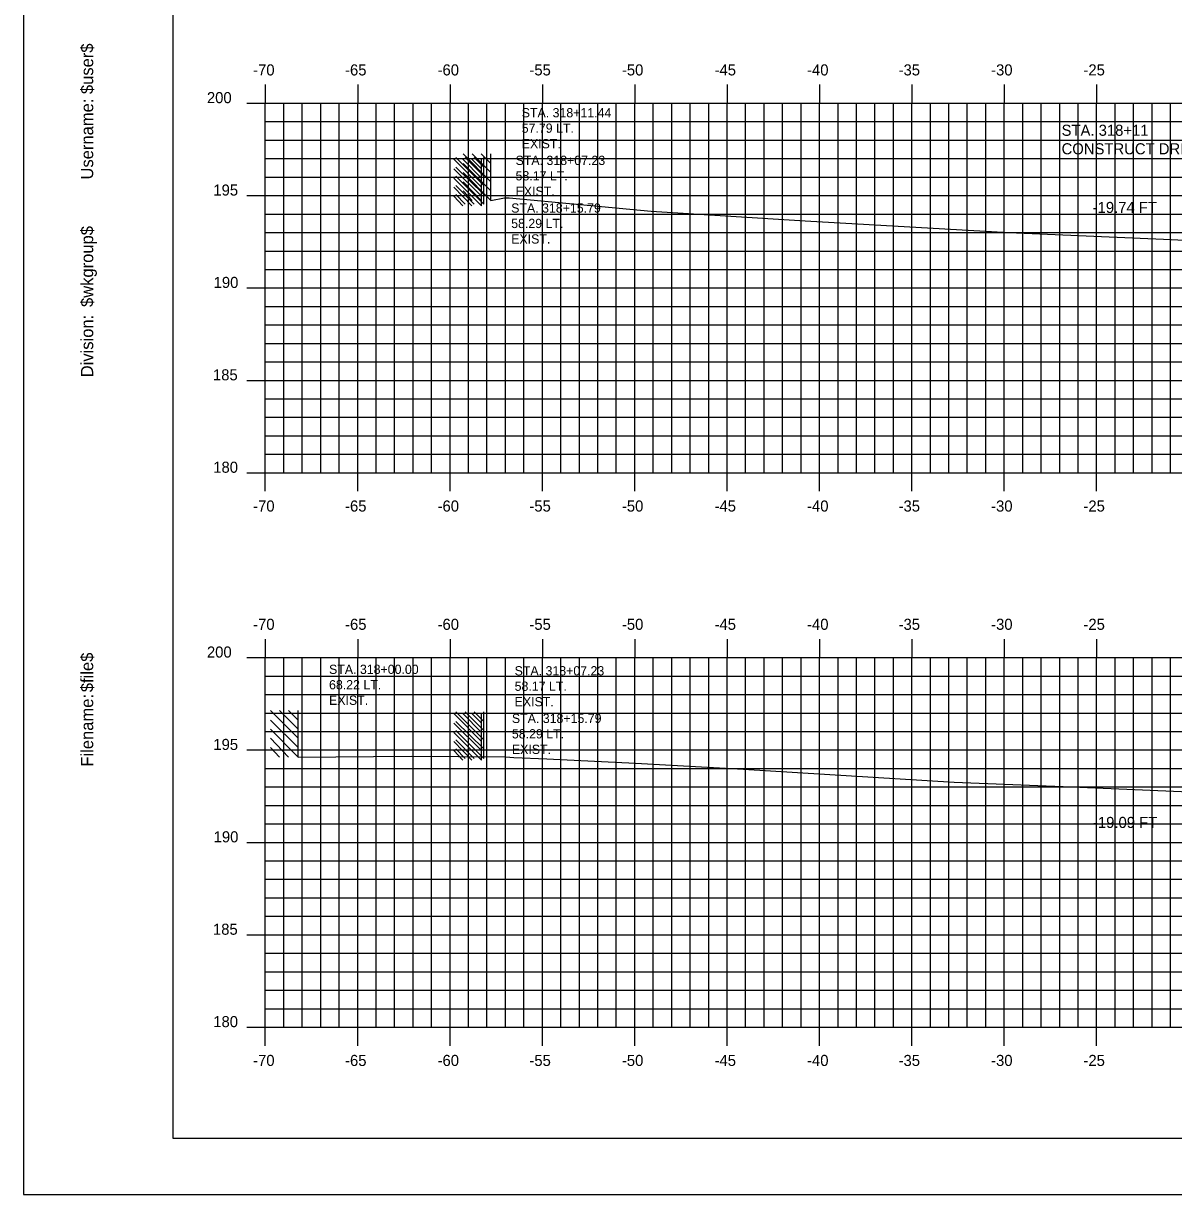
# Model space of a CAD drawing. Extents: x 1139207 to 1139377, y 608981 to 609091.
# Drawn here: x 1139206.6 to 1139268.9, y 608981.3 to 609044.6 of the extents above; entities that cross this region are included whole.
import ezdxf

# ---------------------------------------------------------------- set-up
doc = ezdxf.new("R2010")
doc.units = 0
for name, color, linetype in [('ANNOTATION', 7, 'Continuous'), ('BORDER', 7, 'Continuous'), ('D_Text_Monospaced', 7, 'Continuous'), ('D_Text_Standard', 7, 'Continuous'), ('H_V ANNOTATION', 7, 'Continuous'), ('MAJOR', 7, 'Continuous'), ('MINOR', 7, 'Continuous'), ('PLOT BOUNDARY', 7, 'Continuous'), ('S_Buildings', 7, 'Continuous'), ('S_Buildings_SillElevation', 7, 'Continuous'), ('S_Roadway_Centerline', 7, 'Continuous')]:
    doc.layers.add(name, color=color, linetype=linetype)

msp = doc.modelspace()

# ---------------------------------------------------------------- linework, layer by layer
at = {"layer": 'BORDER'}
msp.add_lwpolyline([(1139214.705, 608984.335), (1139374.705, 608984.335), (1139374.705, 609089.335), (1139214.705, 609089.335)], close=True, dxfattribs=at)
at = {"layer": 'MAJOR'}
for p, q in [((1139219.705, 609041.337), (1139219.705, 609040.335)), ((1139224.705, 609041.337), (1139224.705, 609040.335)), ((1139229.705, 609041.337), (1139229.705, 609040.335)), ((1139234.705, 609041.337), (1139234.705, 609040.335)), ((1139239.705, 609041.337), (1139239.705, 609040.335)), ((1139244.705, 609041.337), (1139244.705, 609040.335)), ((1139249.705, 609041.337), (1139249.705, 609040.335)), ((1139254.705, 609041.337), (1139254.705, 609040.335)), ((1139259.705, 609041.337), (1139259.705, 609040.335)), ((1139264.705, 609041.337), (1139264.705, 609040.335)), ((1139218.703, 609040.335), (1139219.705, 609040.335)), ((1139219.705, 609040.335), (1139359.705, 609040.335)), ((1139219.705, 609020.335), (1139219.705, 609040.335)), ((1139219.705, 609020.335), (1139219.705, 609040.335)), ((1139219.705, 609040.335), (1139359.705, 609040.335)), ((1139224.705, 609020.335), (1139224.705, 609040.335)), ((1139229.705, 609020.335), (1139229.705, 609040.335)), ((1139234.705, 609020.335), (1139234.705, 609040.335)), ((1139239.705, 609020.335), (1139239.705, 609040.335)), ((1139244.705, 609020.335), (1139244.705, 609040.335)), ((1139249.705, 609020.335), (1139249.705, 609040.335)), ((1139254.705, 609020.335), (1139254.705, 609040.335)), ((1139259.705, 609020.335), (1139259.705, 609040.335)), ((1139264.705, 609020.335), (1139264.705, 609040.335)), ((1139218.703, 609035.335), (1139219.705, 609035.335)), ((1139219.705, 609035.335), (1139359.705, 609035.335)), ((1139218.703, 609030.335), (1139219.705, 609030.335)), ((1139219.705, 609030.335), (1139359.705, 609030.335)), ((1139218.703, 609025.335), (1139219.705, 609025.335)), ((1139219.705, 609025.335), (1139359.705, 609025.335)), ((1139218.703, 609020.335), (1139219.705, 609020.335)), ((1139219.705, 609020.335), (1139359.705, 609020.335)), ((1139219.705, 609020.335), (1139359.705, 609020.335)), ((1139219.705, 609019.333), (1139219.705, 609020.335)), ((1139224.705, 609019.333), (1139224.705, 609020.335)), ((1139229.705, 609019.333), (1139229.705, 609020.335)), ((1139234.705, 609019.333), (1139234.705, 609020.335)), ((1139239.705, 609019.333), (1139239.705, 609020.335)), ((1139244.705, 609019.333), (1139244.705, 609020.335)), ((1139249.705, 609019.333), (1139249.705, 609020.335)), ((1139254.705, 609019.333), (1139254.705, 609020.335)), ((1139259.705, 609019.333), (1139259.705, 609020.335)), ((1139264.705, 609019.333), (1139264.705, 609020.335)), ((1139219.705, 609011.337), (1139219.705, 609010.335)), ((1139224.705, 609011.337), (1139224.705, 609010.335)), ((1139229.705, 609011.337), (1139229.705, 609010.335)), ((1139234.705, 609011.337), (1139234.705, 609010.335)), ((1139239.705, 609011.337), (1139239.705, 609010.335)), ((1139244.705, 609011.337), (1139244.705, 609010.335)), ((1139249.705, 609011.337), (1139249.705, 609010.335)), ((1139254.705, 609011.337), (1139254.705, 609010.335)), ((1139259.705, 609011.337), (1139259.705, 609010.335)), ((1139264.705, 609011.337), (1139264.705, 609010.335)), ((1139218.703, 609010.335), (1139219.705, 609010.335)), ((1139219.705, 609010.335), (1139359.705, 609010.335)), ((1139219.705, 608990.335), (1139219.705, 609010.335)), ((1139219.705, 608990.335), (1139219.705, 609010.335)), ((1139219.705, 609010.335), (1139359.705, 609010.335)), ((1139224.705, 608990.335), (1139224.705, 609010.335)), ((1139229.705, 608990.335), (1139229.705, 609010.335)), ((1139234.705, 608990.335), (1139234.705, 609010.335)), ((1139239.705, 608990.335), (1139239.705, 609010.335)), ((1139244.705, 608990.335), (1139244.705, 609010.335)), ((1139249.705, 608990.335), (1139249.705, 609010.335)), ((1139254.705, 608990.335), (1139254.705, 609010.335)), ((1139259.705, 608990.335), (1139259.705, 609010.335)), ((1139264.705, 608990.335), (1139264.705, 609010.335)), ((1139218.703, 609005.335), (1139219.705, 609005.335)), ((1139219.705, 609005.335), (1139359.705, 609005.335)), ((1139218.703, 609000.335), (1139219.705, 609000.335)), ((1139219.705, 609000.335), (1139359.705, 609000.335)), ((1139218.703, 608995.335), (1139219.705, 608995.335)), ((1139219.705, 608995.335), (1139359.705, 608995.335)), ((1139218.703, 608990.335), (1139219.705, 608990.335)), ((1139219.705, 608990.335), (1139359.705, 608990.335)), ((1139219.705, 608990.335), (1139359.705, 608990.335)), ((1139219.705, 608989.333), (1139219.705, 608990.335)), ((1139224.705, 608989.333), (1139224.705, 608990.335)), ((1139229.705, 608989.333), (1139229.705, 608990.335)), ((1139234.705, 608989.333), (1139234.705, 608990.335)), ((1139239.705, 608989.333), (1139239.705, 608990.335)), ((1139244.705, 608989.333), (1139244.705, 608990.335)), ((1139249.705, 608989.333), (1139249.705, 608990.335)), ((1139254.705, 608989.333), (1139254.705, 608990.335)), ((1139259.705, 608989.333), (1139259.705, 608990.335)), ((1139264.705, 608989.333), (1139264.705, 608990.335))]:
    msp.add_line(p, q, dxfattribs=at)
at = {"layer": 'MINOR'}
for p, q in [((1139220.705, 609020.335), (1139220.705, 609040.335)), ((1139221.705, 609020.335), (1139221.705, 609040.335)), ((1139222.705, 609020.335), (1139222.705, 609040.335)), ((1139223.705, 609020.335), (1139223.705, 609040.335)), ((1139225.705, 609020.335), (1139225.705, 609040.335)), ((1139226.705, 609020.335), (1139226.705, 609040.335)), ((1139227.705, 609020.335), (1139227.705, 609040.335)), ((1139228.705, 609020.335), (1139228.705, 609040.335)), ((1139230.705, 609020.335), (1139230.705, 609040.335)), ((1139231.705, 609020.335), (1139231.705, 609040.335)), ((1139232.705, 609020.335), (1139232.705, 609040.335)), ((1139233.705, 609020.335), (1139233.705, 609040.335)), ((1139235.705, 609020.335), (1139235.705, 609040.335)), ((1139236.705, 609020.335), (1139236.705, 609040.335)), ((1139237.705, 609020.335), (1139237.705, 609040.335)), ((1139238.705, 609020.335), (1139238.705, 609040.335)), ((1139240.705, 609020.335), (1139240.705, 609040.335)), ((1139241.705, 609020.335), (1139241.705, 609040.335)), ((1139242.705, 609020.335), (1139242.705, 609040.335)), ((1139243.705, 609020.335), (1139243.705, 609040.335)), ((1139245.705, 609020.335), (1139245.705, 609040.335)), ((1139246.705, 609020.335), (1139246.705, 609040.335)), ((1139247.705, 609020.335), (1139247.705, 609040.335)), ((1139248.705, 609020.335), (1139248.705, 609040.335)), ((1139250.705, 609020.335), (1139250.705, 609040.335)), ((1139251.705, 609020.335), (1139251.705, 609040.335)), ((1139252.705, 609020.335), (1139252.705, 609040.335)), ((1139253.705, 609020.335), (1139253.705, 609040.335)), ((1139255.705, 609020.335), (1139255.705, 609040.335)), ((1139256.705, 609020.335), (1139256.705, 609040.335)), ((1139257.705, 609020.335), (1139257.705, 609040.335)), ((1139258.705, 609020.335), (1139258.705, 609040.335)), ((1139260.705, 609020.335), (1139260.705, 609040.335)), ((1139261.705, 609020.335), (1139261.705, 609040.335)), ((1139262.705, 609020.335), (1139262.705, 609040.335)), ((1139263.705, 609020.335), (1139263.705, 609040.335)), ((1139265.705, 609020.335), (1139265.705, 609040.335)), ((1139266.705, 609020.335), (1139266.705, 609040.335)), ((1139267.705, 609020.335), (1139267.705, 609040.335)), ((1139268.705, 609020.335), (1139268.705, 609040.335)), ((1139219.705, 609039.335), (1139359.705, 609039.335)), ((1139219.705, 609039.335), (1139220.707, 609039.335)), ((1139219.705, 609038.335), (1139359.705, 609038.335)), ((1139219.705, 609038.335), (1139220.707, 609038.335)), ((1139219.705, 609037.335), (1139359.705, 609037.335)), ((1139219.705, 609037.335), (1139220.707, 609037.335)), ((1139219.705, 609036.335), (1139359.705, 609036.335)), ((1139219.705, 609036.335), (1139220.707, 609036.335)), ((1139219.705, 609034.335), (1139359.705, 609034.335)), ((1139219.705, 609034.335), (1139220.707, 609034.335)), ((1139219.705, 609033.335), (1139359.705, 609033.335)), ((1139219.705, 609033.335), (1139220.707, 609033.335)), ((1139219.705, 609032.335), (1139359.705, 609032.335)), ((1139219.705, 609032.335), (1139220.707, 609032.335)), ((1139219.705, 609031.335), (1139359.705, 609031.335)), ((1139219.705, 609031.335), (1139220.707, 609031.335)), ((1139219.705, 609029.335), (1139359.705, 609029.335)), ((1139219.705, 609029.335), (1139220.707, 609029.335)), ((1139219.705, 609028.335), (1139359.705, 609028.335)), ((1139219.705, 609028.335), (1139220.707, 609028.335)), ((1139219.705, 609027.335), (1139359.705, 609027.335)), ((1139219.705, 609027.335), (1139220.707, 609027.335)), ((1139219.705, 609026.335), (1139359.705, 609026.335)), ((1139219.705, 609026.335), (1139220.707, 609026.335)), ((1139219.705, 609024.335), (1139359.705, 609024.335)), ((1139219.705, 609024.335), (1139220.707, 609024.335)), ((1139219.705, 609023.335), (1139359.705, 609023.335)), ((1139219.705, 609023.335), (1139220.707, 609023.335)), ((1139219.705, 609022.335), (1139359.705, 609022.335)), ((1139219.705, 609022.335), (1139220.707, 609022.335)), ((1139219.705, 609021.335), (1139359.705, 609021.335)), ((1139219.705, 609021.335), (1139220.707, 609021.335)), ((1139220.705, 608990.335), (1139220.705, 609010.335)), ((1139221.705, 608990.335), (1139221.705, 609010.335)), ((1139222.705, 608990.335), (1139222.705, 609010.335)), ((1139223.705, 608990.335), (1139223.705, 609010.335)), ((1139225.705, 608990.335), (1139225.705, 609010.335)), ((1139226.705, 608990.335), (1139226.705, 609010.335)), ((1139227.705, 608990.335), (1139227.705, 609010.335)), ((1139228.705, 608990.335), (1139228.705, 609010.335)), ((1139230.705, 608990.335), (1139230.705, 609010.335)), ((1139231.705, 608990.335), (1139231.705, 609010.335)), ((1139232.705, 608990.335), (1139232.705, 609010.335)), ((1139233.705, 608990.335), (1139233.705, 609010.335)), ((1139235.705, 608990.335), (1139235.705, 609010.335)), ((1139236.705, 608990.335), (1139236.705, 609010.335)), ((1139237.705, 608990.335), (1139237.705, 609010.335)), ((1139238.705, 608990.335), (1139238.705, 609010.335)), ((1139240.705, 608990.335), (1139240.705, 609010.335)), ((1139241.705, 608990.335), (1139241.705, 609010.335)), ((1139242.705, 608990.335), (1139242.705, 609010.335)), ((1139243.705, 608990.335), (1139243.705, 609010.335)), ((1139245.705, 608990.335), (1139245.705, 609010.335)), ((1139246.705, 608990.335), (1139246.705, 609010.335)), ((1139247.705, 608990.335), (1139247.705, 609010.335)), ((1139248.705, 608990.335), (1139248.705, 609010.335)), ((1139250.705, 608990.335), (1139250.705, 609010.335)), ((1139251.705, 608990.335), (1139251.705, 609010.335)), ((1139252.705, 608990.335), (1139252.705, 609010.335)), ((1139253.705, 608990.335), (1139253.705, 609010.335)), ((1139255.705, 608990.335), (1139255.705, 609010.335)), ((1139256.705, 608990.335), (1139256.705, 609010.335)), ((1139257.705, 608990.335), (1139257.705, 609010.335)), ((1139258.705, 608990.335), (1139258.705, 609010.335)), ((1139260.705, 608990.335), (1139260.705, 609010.335)), ((1139261.705, 608990.335), (1139261.705, 609010.335)), ((1139262.705, 608990.335), (1139262.705, 609010.335)), ((1139263.705, 608990.335), (1139263.705, 609010.335)), ((1139265.705, 608990.335), (1139265.705, 609010.335)), ((1139266.705, 608990.335), (1139266.705, 609010.335)), ((1139267.705, 608990.335), (1139267.705, 609010.335)), ((1139268.705, 608990.335), (1139268.705, 609010.335)), ((1139219.705, 609009.335), (1139359.705, 609009.335)), ((1139219.705, 609009.335), (1139220.707, 609009.335)), ((1139219.705, 609008.335), (1139359.705, 609008.335)), ((1139219.705, 609008.335), (1139220.707, 609008.335)), ((1139219.705, 609007.335), (1139359.705, 609007.335)), ((1139219.705, 609007.335), (1139220.707, 609007.335)), ((1139219.705, 609006.335), (1139359.705, 609006.335)), ((1139219.705, 609006.335), (1139220.707, 609006.335)), ((1139219.705, 609004.335), (1139359.705, 609004.335)), ((1139219.705, 609004.335), (1139220.707, 609004.335)), ((1139219.705, 609003.335), (1139359.705, 609003.335)), ((1139219.705, 609003.335), (1139220.707, 609003.335)), ((1139219.705, 609002.335), (1139359.705, 609002.335)), ((1139219.705, 609002.335), (1139220.707, 609002.335)), ((1139219.705, 609001.335), (1139359.705, 609001.335)), ((1139219.705, 609001.335), (1139220.707, 609001.335)), ((1139219.705, 608999.335), (1139359.705, 608999.335)), ((1139219.705, 608999.335), (1139220.707, 608999.335)), ((1139219.705, 608998.335), (1139359.705, 608998.335)), ((1139219.705, 608998.335), (1139220.707, 608998.335)), ((1139219.705, 608997.335), (1139359.705, 608997.335)), ((1139219.705, 608997.335), (1139220.707, 608997.335)), ((1139219.705, 608996.335), (1139359.705, 608996.335)), ((1139219.705, 608996.335), (1139220.707, 608996.335)), ((1139219.705, 608994.335), (1139359.705, 608994.335)), ((1139219.705, 608994.335), (1139220.707, 608994.335)), ((1139219.705, 608993.335), (1139359.705, 608993.335)), ((1139219.705, 608993.335), (1139220.707, 608993.335)), ((1139219.705, 608992.335), (1139359.705, 608992.335)), ((1139219.705, 608992.335), (1139220.707, 608992.335)), ((1139219.705, 608991.335), (1139359.705, 608991.335)), ((1139219.705, 608991.335), (1139220.707, 608991.335))]:
    msp.add_line(p, q, dxfattribs=at)
at = {"layer": 'PLOT BOUNDARY'}
msp.add_lwpolyline([(1139206.612, 608981.276), (1139376.612, 608981.276), (1139376.612, 609091.276), (1139206.612, 609091.276)], close=True, dxfattribs=at)
at = {"layer": 'S_Buildings'}
for p, q in [((1139231.918, 609036.085), (1139230.409, 609037.595)), ((1139231.918, 609036.577), (1139230.901, 609037.595)), ((1139231.918, 609037.07), (1139231.393, 609037.595)), ((1139231.918, 609035.068), (1139231.918, 609037.595)), ((1139231.918, 609035.593), (1139230.409, 609037.07)), ((1139231.918, 609035.068), (1139230.409, 609036.577)), ((1139231.393, 609035.068), (1139230.409, 609036.085)), ((1139230.901, 609035.068), (1139230.409, 609035.593)), ((1139221.488, 609005.969), (1139219.979, 609007.478)), ((1139221.488, 609006.461), (1139220.471, 609007.478)), ((1139221.488, 609006.953), (1139220.963, 609007.478)), ((1139221.488, 609004.952), (1139221.488, 609007.478)), ((1139221.488, 609005.477), (1139219.979, 609006.953)), ((1139221.488, 609004.952), (1139219.979, 609006.461)), ((1139220.963, 609004.952), (1139219.979, 609005.969)), ((1139220.471, 609004.952), (1139219.979, 609005.477))]:
    msp.add_line(p, q, dxfattribs=at)
at = {"layer": 'S_Buildings_SillElevation'}
for p, q in [((1139231.412, 609035.792), (1139229.903, 609037.301)), ((1139231.535, 609035.887), (1139230.026, 609037.397)), ((1139231.535, 609035.395), (1139230.026, 609036.872)), ((1139231.412, 609036.284), (1139230.395, 609037.301)), ((1139231.535, 609036.38), (1139230.518, 609037.397)), ((1139231.412, 609036.777), (1139230.887, 609037.301)), ((1139231.535, 609036.872), (1139231.01, 609037.397)), ((1139231.412, 609034.775), (1139231.412, 609037.301)), ((1139231.535, 609034.87), (1139231.535, 609037.397)), ((1139231.412, 609035.3), (1139229.903, 609036.777)), ((1139231.412, 609034.775), (1139229.903, 609036.284)), ((1139231.535, 609034.87), (1139230.026, 609036.38)), ((1139230.887, 609034.775), (1139229.903, 609035.792)), ((1139231.01, 609034.87), (1139230.026, 609035.887)), ((1139230.395, 609034.775), (1139229.903, 609035.3)), ((1139230.518, 609034.87), (1139230.026, 609035.395)), ((1139231.412, 609005.792), (1139229.903, 609007.301)), ((1139231.535, 609005.887), (1139230.026, 609007.397)), ((1139231.412, 609006.284), (1139230.395, 609007.301)), ((1139231.535, 609006.38), (1139230.518, 609007.397)), ((1139231.412, 609006.777), (1139230.887, 609007.301)), ((1139231.535, 609006.872), (1139231.01, 609007.397)), ((1139231.412, 609004.775), (1139231.412, 609007.301)), ((1139231.535, 609004.87), (1139231.535, 609007.397)), ((1139231.412, 609005.3), (1139229.903, 609006.777)), ((1139231.535, 609005.395), (1139230.026, 609006.872)), ((1139231.412, 609004.775), (1139229.903, 609006.284)), ((1139230.887, 609004.775), (1139229.903, 609005.792)), ((1139231.535, 609004.87), (1139230.026, 609006.38)), ((1139231.01, 609004.87), (1139230.026, 609005.887)), ((1139230.395, 609004.775), (1139229.903, 609005.3)), ((1139230.518, 609004.87), (1139230.026, 609005.395))]:
    msp.add_line(p, q, dxfattribs=at)
at = {"layer": 'S_Roadway_Centerline'}
for points in [[(1139231.918, 609035.069), (1139232.651, 609035.216), (1139232.676, 609035.214), (1139232.901, 609035.204), (1139240.591, 609034.488), (1139248.93, 609033.974), (1139259.944, 609033.343), (1139268.743, 609032.962), (1139276.277, 609032.574)], [(1139221.488, 609004.952), (1139227.603, 609004.991), (1139232.725, 609004.958), (1139233.159, 609004.93), (1139234.94, 609004.847), (1139239.749, 609004.617), (1139245.588, 609004.302), (1139256.987, 609003.595), (1139263.803, 609003.317), (1139276.068, 609002.793)]]:
    msp.add_lwpolyline(points, dxfattribs=at)

# ---------------------------------------------------------------- texts
at = {"layer": 'ANNOTATION'}
for s, p in [('STA. 318+11', (1139262.808, 609038.568)), ('CONSTRUCT DRIVEWAY BUTT JOINT', (1139262.808, 609037.566))]:
    msp.add_text(s, height=0.6, dxfattribs=at).set_placement(p)
at = {"layer": 'BORDER'}
for s, p in [('$user$', (1139210.39, 609040.827)), ('Username:', (1139210.39, 609036.203)), ('$wkgroup$', (1139210.39, 609029.305)), ('Division:', (1139210.39, 609025.501)), ('$file$', (1139210.39, 609008.461)), ('Filename:', (1139210.39, 609004.433))]:
    msp.add_text(s, height=0.6696, rotation=90, dxfattribs=at).set_placement(p)
at = {"layer": 'D_Text_Monospaced'}
for s, height, p in [('STA. 318+11.44', 0.49998, (1139233.585, 609039.567)), ('57.79 LT.', 0.5, (1139233.585, 609038.733)), ('EXIST. ', 0.5, (1139233.585, 609037.893)), ('STA. 318+07.23', 0.49998, (1139233.253, 609036.989)), ('58.17 LT.', 0.5, (1139233.253, 609036.155)), ('EXIST. ', 0.5, (1139233.253, 609035.315)), ('STA. 318+15.79', 0.49998, (1139233.015, 609034.411)), ('58.29 LT.', 0.5, (1139233.015, 609033.577)), ('EXIST. ', 0.5, (1139233.015, 609032.737)), ('STA. 318+00.00', 0.49998, (1139223.155, 609009.45)), ('STA. 318+07.23', 0.49998, (1139233.202, 609009.369)), ('68.22 LT.', 0.5, (1139223.155, 609008.616)), ('58.17 LT.', 0.5, (1139233.202, 609008.535)), ('EXIST. ', 0.5, (1139223.155, 609007.776)), ('EXIST. ', 0.5, (1139233.202, 609007.695)), ('STA. 318+15.79', 0.49998, (1139233.053, 609006.793)), ('58.29 LT.', 0.5, (1139233.053, 609005.959)), ('EXIST. ', 0.5, (1139233.053, 609005.119))]:
    msp.add_text(s, height=height, dxfattribs=at).set_placement(p)
at = {"layer": 'D_Text_Standard'}
for s, p in [('-19.74 FT', (1139264.49, 609034.392)), ('-19.09 FT', (1139264.507, 609001.114))]:
    msp.add_text(s, height=0.6, dxfattribs=at).set_placement(p)
at = {"layer": 'H_V ANNOTATION'}
for s, p in [('-70', (1139219.047, 609041.835)), ('-65', (1139224.023, 609041.835)), ('-60', (1139229.031, 609041.835)), ('-55', (1139234.001, 609041.835)), ('-50', (1139239.009, 609041.835)), ('-45', (1139244.023, 609041.835)), ('-40', (1139249.031, 609041.835)), ('-35', (1139253.985, 609041.835)), ('-30', (1139258.993, 609041.835)), ('-25', (1139263.991, 609041.835)), ('200', (1139216.546, 609040.335)), ('195', (1139216.894, 609035.335)), ('190', (1139216.91, 609030.335)), ('185', (1139216.873, 609025.335)), ('180', (1139216.889, 609020.335)), ('-70', (1139219.047, 609018.235)), ('-65', (1139224.023, 609018.235)), ('-60', (1139229.031, 609018.235)), ('-55', (1139234.001, 609018.235)), ('-50', (1139239.009, 609018.235)), ('-45', (1139244.023, 609018.235)), ('-40', (1139249.031, 609018.235)), ('-35', (1139253.985, 609018.235)), ('-30', (1139258.993, 609018.235)), ('-25', (1139263.991, 609018.235)), ('-70', (1139219.047, 609011.835)), ('-65', (1139224.023, 609011.835)), ('-60', (1139229.031, 609011.835)), ('-55', (1139234.001, 609011.835)), ('-50', (1139239.009, 609011.835)), ('-45', (1139244.023, 609011.835)), ('-40', (1139249.031, 609011.835)), ('-35', (1139253.985, 609011.835)), ('-30', (1139258.993, 609011.835)), ('-25', (1139263.991, 609011.835)), ('200', (1139216.546, 609010.335)), ('195', (1139216.894, 609005.335)), ('190', (1139216.91, 609000.335)), ('185', (1139216.873, 608995.335)), ('180', (1139216.889, 608990.335)), ('-70', (1139219.047, 608988.235)), ('-65', (1139224.023, 608988.235)), ('-60', (1139229.031, 608988.235)), ('-55', (1139234.001, 608988.235)), ('-50', (1139239.009, 608988.235)), ('-45', (1139244.023, 608988.235)), ('-40', (1139249.031, 608988.235)), ('-35', (1139253.985, 608988.235)), ('-30', (1139258.993, 608988.235)), ('-25', (1139263.991, 608988.235))]:
    msp.add_text(s, height=0.6, dxfattribs=at).set_placement(p)
at = {"layer": 'MAJOR'}
for p in [(1139219.701, 609020.335), (1139219.701, 608990.335)]:
    msp.add_text('-', height=0.006, dxfattribs=at).set_placement(p)

doc.saveas('drawing.dxf')
